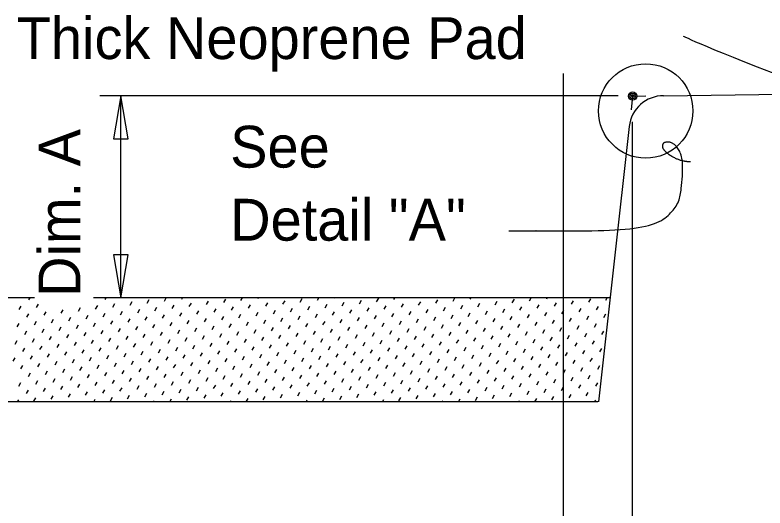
# Model space of a CAD drawing. Extents: x 21516.9 to 21589, y 56156.6 to 56194.3.
# Drawn here: x 21522.743 to 21526.357, y 56182.2 to 56184.575 of the extents above; entities that cross this region are included whole.
import ezdxf

# ---------------------------------------------------------------- set-up
doc = ezdxf.new("R2010")
doc.units = 0
for name, color, linetype in [('AdhocPoint_dp', 7, 'Continuous'), ('Patterning', 7, 'Continuous'), ('PlotBorder_dp', 7, 'Continuous'), ('SheetBorder_dp', 7, 'Continuous')]:
    doc.layers.add(name, color=color, linetype=linetype)

msp = doc.modelspace()

# ---------------------------------------------------------------- linework, layer by layer
at = {"layer": 'AdhocPoint_dp'}
for p, q in [((21525.8686, 56184.1864), (21531.5524, 56184.2643)), ((21525.703, 56184.0381), (21525.5556, 56182.7117)), ((21525.5524, 56182.7117), (21521.6191, 56182.7117))]:
    msp.add_line(p, q, dxfattribs=at)
msp.add_arc((21525.8686, 56184.0197), 0.1667, 90, 173.6598, dxfattribs=at)
at = {"layer": 'Patterning'}
for p, q in [((21522.8378, 56183.2117), (21521.6191, 56183.2117)), ((21522.8099, 56183.2019), (21522.8156, 56183.2117)), ((21522.8465, 56183.1652), (21522.8562, 56183.182)), ((21525.6112, 56183.2117), (21523.1214, 56183.2117)), ((21523.1783, 56183.2041), (21523.1827, 56183.2117)), ((21523.2149, 56183.1675), (21523.2246, 56183.1843)), ((21523.2978, 56183.1773), (21523.3075, 56183.194)), ((21523.3808, 56183.187), (21523.3905, 56183.2038)), ((21523.4637, 56183.1967), (21523.4724, 56183.2117)), ((21523.5466, 56183.2064), (21523.5497, 56183.2117)), ((21523.5832, 56183.1698), (21523.593, 56183.1866)), ((21523.6662, 56183.1795), (21523.6759, 56183.1963)), ((21523.7491, 56183.1893), (21523.7588, 56183.2061)), ((21523.8321, 56183.199), (21523.8394, 56183.2117)), ((21523.8687, 56183.1624), (21523.8784, 56183.1792)), ((21523.915, 56183.2087), (21523.9167, 56183.2117)), ((21523.9516, 56183.1721), (21523.9613, 56183.1889)), ((21524.0345, 56183.1818), (21524.0443, 56183.1986)), ((21524.1175, 56183.1915), (21524.1272, 56183.2083)), ((21524.2004, 56183.2013), (21524.2065, 56183.2117)), ((21524.237, 56183.1647), (21524.2467, 56183.1814)), ((21524.2833, 56183.211), (21524.2838, 56183.2117)), ((21524.32, 56183.1744), (21524.3297, 56183.1912)), ((21524.4029, 56183.1841), (21524.4126, 56183.2009)), ((21524.4858, 56183.1938), (21524.4956, 56183.2106)), ((21524.5688, 56183.2035), (21524.5735, 56183.2117)), ((21524.6054, 56183.1669), (21524.6151, 56183.1837)), ((21524.6883, 56183.1767), (21524.698, 56183.1935)), ((21524.7713, 56183.1864), (21524.781, 56183.2032)), ((21524.8542, 56183.1961), (21524.8632, 56183.2117)), ((21524.9371, 56183.2058), (21524.9405, 56183.2117)), ((21524.9737, 56183.1692), (21524.9835, 56183.186)), ((21525.0567, 56183.1789), (21525.0664, 56183.1957)), ((21525.1396, 56183.1887), (21525.1493, 56183.2055)), ((21525.2225, 56183.1984), (21525.2303, 56183.2117)), ((21525.2592, 56183.1618), (21525.2689, 56183.1786)), ((21525.3055, 56183.2081), (21525.3076, 56183.2117)), ((21525.3421, 56183.1715), (21525.3518, 56183.1883)), ((21525.425, 56183.1812), (21525.4348, 56183.198)), ((21525.508, 56183.191), (21525.5177, 56183.2077)), ((21525.5909, 56183.2007), (21525.5973, 56183.2117)), ((21522.7636, 56183.1555), (21522.7733, 56183.1723)), ((21522.8831, 56183.1286), (21522.8929, 56183.1454)), ((21522.9661, 56183.1384), (21522.9758, 56183.1552)), ((21523.049, 56183.1481), (21523.0587, 56183.1649)), ((21523.1319, 56183.1578), (21523.1417, 56183.1746)), ((21523.2515, 56183.1309), (21523.2612, 56183.1477)), ((21523.3344, 56183.1406), (21523.3441, 56183.1574)), ((21523.4174, 56183.1504), (21523.4271, 56183.1672)), ((21523.5003, 56183.1601), (21523.51, 56183.1769)), ((21523.6198, 56183.1332), (21523.6296, 56183.15)), ((21523.7028, 56183.1429), (21523.7125, 56183.1597)), ((21523.7857, 56183.1526), (21523.7954, 56183.1694)), ((21523.9053, 56183.1258), (21523.915, 56183.1426)), ((21523.9882, 56183.1355), (21523.9979, 56183.1523)), ((21524.0711, 56183.1452), (21524.0809, 56183.162)), ((21524.1541, 56183.1549), (21524.1638, 56183.1717)), ((21524.2736, 56183.128), (21524.2833, 56183.1448)), ((21524.3566, 56183.1378), (21524.3663, 56183.1546)), ((21524.4395, 56183.1475), (21524.4492, 56183.1643)), ((21524.5224, 56183.1572), (21524.5322, 56183.174)), ((21524.642, 56183.1303), (21524.6517, 56183.1471)), ((21524.7249, 56183.1401), (21524.7346, 56183.1568)), ((21524.8079, 56183.1498), (21524.8176, 56183.1666)), ((21524.8908, 56183.1595), (21524.9005, 56183.1763)), ((21525.0103, 56183.1326), (21525.0201, 56183.1494)), ((21525.0933, 56183.1423), (21525.103, 56183.1591)), ((21525.1762, 56183.1521), (21525.1859, 56183.1689)), ((21525.2958, 56183.1252), (21525.3055, 56183.142)), ((21525.3787, 56183.1349), (21525.3884, 56183.1517)), ((21525.4616, 56183.1446), (21525.4714, 56183.1614)), ((21525.5446, 56183.1543), (21525.5543, 56183.1711)), ((21522.8002, 56183.1189), (21522.8099, 56183.1357)), ((21522.9197, 56183.092), (21522.9295, 56183.1088)), ((21523.0027, 56183.1018), (21523.0124, 56183.1185)), ((21523.0856, 56183.1115), (21523.0953, 56183.1283)), ((21523.1685, 56183.1212), (21523.1783, 56183.138)), ((21523.2881, 56183.0943), (21523.2978, 56183.1111)), ((21523.371, 56183.104), (21523.3808, 56183.1208)), ((21523.454, 56183.1138), (21523.4637, 56183.1306)), ((21523.5369, 56183.1235), (21523.5466, 56183.1403)), ((21523.6565, 56183.0966), (21523.6662, 56183.1134)), ((21523.7394, 56183.1063), (21523.7491, 56183.1231)), ((21523.8223, 56183.116), (21523.8321, 56183.1328)), ((21523.9419, 56183.0892), (21523.9516, 56183.106)), ((21524.0248, 56183.0989), (21524.0345, 56183.1157)), ((21524.1077, 56183.1086), (21524.1175, 56183.1254)), ((21524.1907, 56183.1183), (21524.2004, 56183.1351)), ((21524.3102, 56183.0914), (21524.32, 56183.1082)), ((21524.3932, 56183.1012), (21524.4029, 56183.118)), ((21524.4761, 56183.1109), (21524.4858, 56183.1277)), ((21524.559, 56183.1206), (21524.5688, 56183.1374)), ((21524.6786, 56183.0937), (21524.6883, 56183.1105)), ((21524.7615, 56183.1034), (21524.7713, 56183.1202)), ((21524.8445, 56183.1132), (21524.8542, 56183.13)), ((21524.9274, 56183.1229), (21524.9371, 56183.1397)), ((21525.0469, 56183.096), (21525.0567, 56183.1128)), ((21525.1299, 56183.1057), (21525.1396, 56183.1225)), ((21525.2128, 56183.1155), (21525.2225, 56183.1322)), ((21525.3324, 56183.0886), (21525.3421, 56183.1054)), ((21525.4153, 56183.0983), (21525.425, 56183.1151)), ((21525.4982, 56183.108), (21525.508, 56183.1248)), ((21525.5812, 56183.1177), (21525.5909, 56183.1345)), ((21522.7539, 56183.0726), (21522.7636, 56183.0894)), ((21522.8368, 56183.0823), (21522.8465, 56183.0991)), ((21522.9563, 56183.0554), (21522.9661, 56183.0722)), ((21523.0393, 56183.0651), (21523.049, 56183.0819)), ((21523.1222, 56183.0749), (21523.1319, 56183.0917)), ((21523.2052, 56183.0846), (21523.2149, 56183.1014)), ((21523.3247, 56183.0577), (21523.3344, 56183.0745)), ((21523.4076, 56183.0674), (21523.4174, 56183.0842)), ((21523.4906, 56183.0772), (21523.5003, 56183.0939)), ((21523.5735, 56183.0869), (21523.5832, 56183.1037)), ((21523.6931, 56183.06), (21523.7028, 56183.0768)), ((21523.776, 56183.0697), (21523.7857, 56183.0865)), ((21523.8589, 56183.0794), (21523.8687, 56183.0962)), ((21523.9785, 56183.0525), (21523.9882, 56183.0693)), ((21524.0614, 56183.0623), (21524.0711, 56183.0791)), ((21524.1444, 56183.072), (21524.1541, 56183.0888)), ((21524.2273, 56183.0817), (21524.237, 56183.0985)), ((21524.3468, 56183.0548), (21524.3566, 56183.0716)), ((21524.4298, 56183.0646), (21524.4395, 56183.0813)), ((21524.5127, 56183.0743), (21524.5224, 56183.0911)), ((21524.5957, 56183.084), (21524.6054, 56183.1008)), ((21524.7152, 56183.0571), (21524.7249, 56183.0739)), ((21524.7981, 56183.0668), (21524.8079, 56183.0836)), ((21524.8811, 56183.0766), (21524.8908, 56183.0934)), ((21524.964, 56183.0863), (21524.9737, 56183.1031)), ((21525.0836, 56183.0594), (21525.0933, 56183.0762)), ((21525.1665, 56183.0691), (21525.1762, 56183.0859)), ((21525.2494, 56183.0788), (21525.2592, 56183.0956)), ((21525.369, 56183.052), (21525.3787, 56183.0688)), ((21525.4519, 56183.0617), (21525.4616, 56183.0785)), ((21525.5349, 56183.0714), (21525.5446, 56183.0882)), ((21522.7905, 56183.036), (21522.8002, 56183.0528)), ((21522.8734, 56183.0457), (21522.8831, 56183.0625)), ((21522.993, 56183.0188), (21523.0027, 56183.0356)), ((21523.0759, 56183.0285), (21523.0856, 56183.0453)), ((21523.1588, 56183.0383), (21523.1685, 56183.0551)), ((21523.2418, 56183.048), (21523.2515, 56183.0648)), ((21523.3613, 56183.0211), (21523.371, 56183.0379)), ((21523.4442, 56183.0308), (21523.454, 56183.0476)), ((21523.5272, 56183.0405), (21523.5369, 56183.0573)), ((21523.6101, 56183.0503), (21523.6198, 56183.0671)), ((21523.7297, 56183.0234), (21523.7394, 56183.0402)), ((21523.8126, 56183.0331), (21523.8223, 56183.0499)), ((21523.8955, 56183.0428), (21523.9053, 56183.0596)), ((21524.0151, 56183.0159), (21524.0248, 56183.0327)), ((21524.098, 56183.0257), (21524.1077, 56183.0425)), ((21524.181, 56183.0354), (21524.1907, 56183.0522)), ((21524.2639, 56183.0451), (21524.2736, 56183.0619)), ((21524.3834, 56183.0182), (21524.3932, 56183.035)), ((21524.4664, 56183.0279), (21524.4761, 56183.0447)), ((21524.5493, 56183.0377), (21524.559, 56183.0545)), ((21524.6323, 56183.0474), (21524.642, 56183.0642)), ((21524.7518, 56183.0205), (21524.7615, 56183.0373)), ((21524.8347, 56183.0302), (21524.8445, 56183.047)), ((21524.9177, 56183.04), (21524.9274, 56183.0567)), ((21525.0006, 56183.0497), (21525.0103, 56183.0665)), ((21525.1202, 56183.0228), (21525.1299, 56183.0396)), ((21525.2031, 56183.0325), (21525.2128, 56183.0493)), ((21525.286, 56183.0422), (21525.2958, 56183.059)), ((21525.4885, 56183.0251), (21525.4982, 56183.0419)), ((21525.5715, 56183.0348), (21525.5812, 56183.0516)), ((21522.7441, 56182.9896), (21522.7539, 56183.0064)), ((21522.8271, 56182.9994), (21522.8368, 56183.0162)), ((21522.91, 56183.0091), (21522.9197, 56183.0259)), ((21523.0296, 56182.9822), (21523.0393, 56182.999)), ((21523.1125, 56182.9919), (21523.1222, 56183.0087)), ((21523.1954, 56183.0017), (21523.2052, 56183.0184)), ((21523.2784, 56183.0114), (21523.2881, 56183.0282)), ((21523.3979, 56182.9845), (21523.4076, 56183.0013)), ((21523.4809, 56182.9942), (21523.4906, 56183.011)), ((21523.5638, 56183.0039), (21523.5735, 56183.0207)), ((21523.6467, 56183.0137), (21523.6565, 56183.0305)), ((21523.7663, 56182.9868), (21523.776, 56183.0036)), ((21523.8492, 56182.9965), (21523.8589, 56183.0133)), ((21523.9322, 56183.0062), (21523.9419, 56183.023)), ((21524.1346, 56182.9891), (21524.1444, 56183.0059)), ((21524.2176, 56182.9988), (21524.2273, 56183.0156)), ((21524.3005, 56183.0085), (21524.3102, 56183.0253)), ((21524.4201, 56182.9816), (21524.4298, 56182.9984)), ((21524.503, 56182.9913), (21524.5127, 56183.0081)), ((21524.5859, 56183.0011), (21524.5957, 56183.0179)), ((21524.6689, 56183.0108), (21524.6786, 56183.0276)), ((21524.7884, 56182.9839), (21524.7981, 56183.0007)), ((21524.8713, 56182.9936), (21524.8811, 56183.0104)), ((21524.9543, 56183.0033), (21524.964, 56183.0201)), ((21525.0372, 56183.0131), (21525.0469, 56183.0299)), ((21525.1568, 56182.9862), (21525.1665, 56183.003)), ((21525.2397, 56182.9959), (21525.2494, 56183.0127)), ((21525.3226, 56183.0056), (21525.3324, 56183.0224)), ((21525.4056, 56183.0154), (21525.4153, 56183.0321)), ((21525.5251, 56182.9885), (21525.5349, 56183.0053)), ((21522.7807, 56182.953), (21522.7905, 56182.9698)), ((21522.8637, 56182.9628), (21522.8734, 56182.9796)), ((21522.9466, 56182.9725), (21522.9563, 56182.9893)), ((21523.0662, 56182.9456), (21523.0759, 56182.9624)), ((21523.1491, 56182.9553), (21523.1588, 56182.9721)), ((21523.232, 56182.965), (21523.2418, 56182.9818)), ((21523.315, 56182.9748), (21523.3247, 56182.9916)), ((21523.4345, 56182.9479), (21523.4442, 56182.9647)), ((21523.5175, 56182.9576), (21523.5272, 56182.9744)), ((21523.6004, 56182.9673), (21523.6101, 56182.9841)), ((21523.6833, 56182.9771), (21523.6931, 56182.9938)), ((21523.8029, 56182.9502), (21523.8126, 56182.967)), ((21523.8858, 56182.9599), (21523.8955, 56182.9767)), ((21523.9688, 56182.9696), (21523.9785, 56182.9864)), ((21524.0517, 56182.9793), (21524.0614, 56182.9961)), ((21524.1712, 56182.9525), (21524.181, 56182.9692)), ((21524.2542, 56182.9622), (21524.2639, 56182.979)), ((21524.3371, 56182.9719), (21524.3468, 56182.9887)), ((21524.4567, 56182.945), (21524.4664, 56182.9618)), ((21524.5396, 56182.9547), (21524.5493, 56182.9715)), ((21524.6225, 56182.9645), (21524.6323, 56182.9812)), ((21524.7055, 56182.9742), (21524.7152, 56182.991)), ((21524.825, 56182.9473), (21524.8347, 56182.9641)), ((21524.908, 56182.957), (21524.9177, 56182.9738)), ((21524.9909, 56182.9667), (21525.0006, 56182.9835)), ((21525.0738, 56182.9765), (21525.0836, 56182.9933)), ((21525.1934, 56182.9496), (21525.2031, 56182.9664)), ((21525.2763, 56182.9593), (21525.286, 56182.9761)), ((21525.3593, 56182.969), (21525.369, 56182.9858)), ((21525.4422, 56182.9787), (21525.4519, 56182.9955)), ((21525.5617, 56182.9519), (21525.5715, 56182.9687)), ((21522.8174, 56182.9164), (21522.8271, 56182.9332)), ((21522.9003, 56182.9262), (21522.91, 56182.9429)), ((21522.9832, 56182.9359), (21522.993, 56182.9527)), ((21523.1028, 56182.909), (21523.1125, 56182.9258)), ((21523.1857, 56182.9187), (21523.1954, 56182.9355)), ((21523.2686, 56182.9284), (21523.2784, 56182.9452)), ((21523.3516, 56182.9382), (21523.3613, 56182.955)), ((21523.4711, 56182.9113), (21523.4809, 56182.9281)), ((21523.5541, 56182.921), (21523.5638, 56182.9378)), ((21523.637, 56182.9307), (21523.6467, 56182.9475)), ((21523.7199, 56182.9404), (21523.7297, 56182.9572)), ((21523.8395, 56182.9136), (21523.8492, 56182.9304)), ((21523.9224, 56182.9233), (21523.9322, 56182.9401)), ((21524.0054, 56182.933), (21524.0151, 56182.9498)), ((21524.0883, 56182.9427), (21524.098, 56182.9595)), ((21524.2078, 56182.9158), (21524.2176, 56182.9326)), ((21524.2908, 56182.9256), (21524.3005, 56182.9424)), ((21524.3737, 56182.9353), (21524.3834, 56182.9521)), ((21524.4933, 56182.9084), (21524.503, 56182.9252)), ((21524.5762, 56182.9181), (21524.5859, 56182.9349)), ((21524.6591, 56182.9278), (21524.6689, 56182.9446)), ((21524.7421, 56182.9376), (21524.7518, 56182.9544)), ((21524.8616, 56182.9107), (21524.8713, 56182.9275)), ((21524.9446, 56182.9204), (21524.9543, 56182.9372)), ((21525.0275, 56182.9301), (21525.0372, 56182.9469)), ((21525.1104, 56182.9399), (21525.1202, 56182.9566)), ((21525.23, 56182.913), (21525.2397, 56182.9298)), ((21525.3129, 56182.9227), (21525.3226, 56182.9395)), ((21525.3959, 56182.9324), (21525.4056, 56182.9492)), ((21525.4788, 56182.9421), (21525.4885, 56182.9589)), ((21522.7344, 56182.9067), (21522.7441, 56182.9235)), ((21522.854, 56182.8798), (21522.8637, 56182.8966)), ((21522.9369, 56182.8895), (21522.9466, 56182.9063)), ((21523.0198, 56182.8993), (21523.0296, 56182.9161)), ((21523.1394, 56182.8724), (21523.1491, 56182.8892)), ((21523.2223, 56182.8821), (21523.232, 56182.8989)), ((21523.3053, 56182.8918), (21523.315, 56182.9086)), ((21523.3882, 56182.9016), (21523.3979, 56182.9183)), ((21523.5077, 56182.8747), (21523.5175, 56182.8915)), ((21523.5907, 56182.8844), (21523.6004, 56182.9012)), ((21523.6736, 56182.8941), (21523.6833, 56182.9109)), ((21523.7566, 56182.9038), (21523.7663, 56182.9206)), ((21523.8761, 56182.877), (21523.8858, 56182.8937)), ((21523.959, 56182.8867), (21523.9688, 56182.9035)), ((21524.042, 56182.8964), (21524.0517, 56182.9132)), ((21524.1249, 56182.9061), (21524.1346, 56182.9229)), ((21524.2445, 56182.8792), (21524.2542, 56182.896)), ((21524.3274, 56182.889), (21524.3371, 56182.9058)), ((21524.4103, 56182.8987), (21524.4201, 56182.9155)), ((21524.5299, 56182.8718), (21524.5396, 56182.8886)), ((21524.6128, 56182.8815), (21524.6225, 56182.8983)), ((21524.6958, 56182.8912), (21524.7055, 56182.908)), ((21524.7787, 56182.901), (21524.7884, 56182.9178)), ((21524.8982, 56182.8741), (21524.908, 56182.8909)), ((21524.9812, 56182.8838), (21524.9909, 56182.9006)), ((21525.0641, 56182.8935), (21525.0738, 56182.9103)), ((21525.147, 56182.9032), (21525.1568, 56182.92)), ((21525.2666, 56182.8764), (21525.2763, 56182.8932)), ((21525.3495, 56182.8861), (21525.3593, 56182.9029)), ((21525.4325, 56182.8958), (21525.4422, 56182.9126)), ((21525.5154, 56182.9055), (21525.5251, 56182.9223)), ((21522.771, 56182.8701), (21522.7807, 56182.8869)), ((21522.8906, 56182.8432), (21522.9003, 56182.86)), ((21522.9735, 56182.8529), (21522.9832, 56182.8697)), ((21523.0564, 56182.8627), (21523.0662, 56182.8795)), ((21523.176, 56182.8358), (21523.1857, 56182.8526)), ((21523.2589, 56182.8455), (21523.2686, 56182.8623)), ((21523.3419, 56182.8552), (21523.3516, 56182.872)), ((21523.4248, 56182.8649), (21523.4345, 56182.8817)), ((21523.5443, 56182.8381), (21523.5541, 56182.8549)), ((21523.6273, 56182.8478), (21523.637, 56182.8646)), ((21523.7102, 56182.8575), (21523.7199, 56182.8743)), ((21523.7932, 56182.8672), (21523.8029, 56182.884)), ((21523.9127, 56182.8403), (21523.9224, 56182.8571)), ((21523.9956, 56182.8501), (21524.0054, 56182.8669)), ((21524.0786, 56182.8598), (21524.0883, 56182.8766)), ((21524.1615, 56182.8695), (21524.1712, 56182.8863)), ((21524.2811, 56182.8426), (21524.2908, 56182.8594)), ((21524.364, 56182.8524), (21524.3737, 56182.8691)), ((21524.4469, 56182.8621), (21524.4567, 56182.8789)), ((21524.5665, 56182.8352), (21524.5762, 56182.852)), ((21524.6494, 56182.8449), (21524.6591, 56182.8617)), ((21524.7324, 56182.8546), (21524.7421, 56182.8714)), ((21524.8153, 56182.8644), (21524.825, 56182.8812)), ((21524.9348, 56182.8375), (21524.9446, 56182.8543)), ((21525.0178, 56182.8472), (21525.0275, 56182.864)), ((21525.1007, 56182.8569), (21525.1104, 56182.8737)), ((21525.1837, 56182.8666), (21525.1934, 56182.8834)), ((21525.3032, 56182.8398), (21525.3129, 56182.8565)), ((21525.3861, 56182.8495), (21525.3959, 56182.8663)), ((21525.4691, 56182.8592), (21525.4788, 56182.876)), ((21525.552, 56182.8689), (21525.5617, 56182.8857)), ((21522.8076, 56182.8335), (21522.8174, 56182.8503)), ((21522.9272, 56182.8066), (21522.9369, 56182.8234)), ((21523.0101, 56182.8163), (21523.0198, 56182.8331)), ((21523.0931, 56182.8261), (21523.1028, 56182.8428)), ((21523.2126, 56182.7992), (21523.2223, 56182.816)), ((21523.2955, 56182.8089), (21523.3053, 56182.8257)), ((21523.3785, 56182.8186), (21523.3882, 56182.8354)), ((21523.4614, 56182.8283), (21523.4711, 56182.8451)), ((21523.581, 56182.8015), (21523.5907, 56182.8182)), ((21523.6639, 56182.8112), (21523.6736, 56182.828)), ((21523.7468, 56182.8209), (21523.7566, 56182.8377)), ((21523.8298, 56182.8306), (21523.8395, 56182.8474)), ((21523.9493, 56182.8037), (21523.959, 56182.8205)), ((21524.0322, 56182.8135), (21524.042, 56182.8303)), ((21524.1152, 56182.8232), (21524.1249, 56182.84)), ((21524.1981, 56182.8329), (21524.2078, 56182.8497)), ((21524.3177, 56182.806), (21524.3274, 56182.8228)), ((21524.4006, 56182.8157), (21524.4103, 56182.8325)), ((21524.4835, 56182.8255), (21524.4933, 56182.8423)), ((21524.686, 56182.8083), (21524.6958, 56182.8251)), ((21524.769, 56182.818), (21524.7787, 56182.8348)), ((21524.8519, 56182.8277), (21524.8616, 56182.8445)), ((21524.9714, 56182.8009), (21524.9812, 56182.8177)), ((21525.0544, 56182.8106), (21525.0641, 56182.8274)), ((21525.1373, 56182.8203), (21525.147, 56182.8371)), ((21525.2203, 56182.83), (21525.23, 56182.8468)), ((21525.3398, 56182.8031), (21525.3495, 56182.8199)), ((21525.4227, 56182.8129), (21525.4325, 56182.8297)), ((21525.5057, 56182.8226), (21525.5154, 56182.8394)), ((21522.7613, 56182.7872), (21522.771, 56182.804)), ((21522.8442, 56182.7969), (21522.854, 56182.8137)), ((21522.9638, 56182.77), (21522.9735, 56182.7868)), ((21523.0467, 56182.7797), (21523.0564, 56182.7965)), ((21523.1297, 56182.7894), (21523.1394, 56182.8062)), ((21523.3321, 56182.7723), (21523.3419, 56182.7891)), ((21523.4151, 56182.782), (21523.4248, 56182.7988)), ((21523.498, 56182.7917), (21523.5077, 56182.8085)), ((21523.6176, 56182.7648), (21523.6273, 56182.7816)), ((21523.7005, 56182.7746), (21523.7102, 56182.7914)), ((21523.7834, 56182.7843), (21523.7932, 56182.8011)), ((21523.8664, 56182.794), (21523.8761, 56182.8108)), ((21523.9859, 56182.7671), (21523.9956, 56182.7839)), ((21524.0689, 56182.7769), (21524.0786, 56182.7936)), ((21524.1518, 56182.7866), (21524.1615, 56182.8034)), ((21524.2347, 56182.7963), (21524.2445, 56182.8131)), ((21524.3543, 56182.7694), (21524.364, 56182.7862)), ((21524.4372, 56182.7791), (21524.4469, 56182.7959)), ((21524.5202, 56182.7889), (21524.5299, 56182.8057)), ((21524.6031, 56182.7986), (21524.6128, 56182.8154)), ((21524.7226, 56182.7717), (21524.7324, 56182.7885)), ((21524.8056, 56182.7814), (21524.8153, 56182.7982)), ((21524.8885, 56182.7911), (21524.8982, 56182.8079)), ((21525.0081, 56182.7643), (21525.0178, 56182.7811)), ((21525.091, 56182.774), (21525.1007, 56182.7908)), ((21525.1739, 56182.7837), (21525.1837, 56182.8005)), ((21525.2569, 56182.7934), (21525.2666, 56182.8102)), ((21525.3764, 56182.7665), (21525.3861, 56182.7833)), ((21525.4594, 56182.7763), (21525.4691, 56182.7931)), ((21525.5423, 56182.786), (21525.552, 56182.8028)), ((21522.7979, 56182.7506), (21522.8076, 56182.7674)), ((21522.8808, 56182.7603), (21522.8906, 56182.7771)), ((21523.0004, 56182.7334), (21523.0101, 56182.7502)), ((21523.0833, 56182.7431), (21523.0931, 56182.7599)), ((21523.1663, 56182.7528), (21523.176, 56182.7696)), ((21523.2492, 56182.7626), (21523.2589, 56182.7794)), ((21523.3687, 56182.7357), (21523.3785, 56182.7525)), ((21523.4517, 56182.7454), (21523.4614, 56182.7622)), ((21523.5346, 56182.7551), (21523.5443, 56182.7719)), ((21523.6542, 56182.7282), (21523.6639, 56182.745)), ((21523.7371, 56182.738), (21523.7468, 56182.7548)), ((21523.82, 56182.7477), (21523.8298, 56182.7645)), ((21523.903, 56182.7574), (21523.9127, 56182.7742)), ((21524.0225, 56182.7305), (21524.0322, 56182.7473)), ((21524.1055, 56182.7402), (21524.1152, 56182.757)), ((21524.1884, 56182.75), (21524.1981, 56182.7668)), ((21524.2713, 56182.7597), (21524.2811, 56182.7765)), ((21524.3909, 56182.7328), (21524.4006, 56182.7496)), ((21524.4738, 56182.7425), (21524.4835, 56182.7593)), ((21524.5568, 56182.7523), (21524.5665, 56182.769)), ((21524.6397, 56182.762), (21524.6494, 56182.7788)), ((21524.7592, 56182.7351), (21524.769, 56182.7519)), ((21524.8422, 56182.7448), (21524.8519, 56182.7616)), ((21524.9251, 56182.7545), (21524.9348, 56182.7713)), ((21525.0447, 56182.7276), (21525.0544, 56182.7444)), ((21525.1276, 56182.7374), (21525.1373, 56182.7542)), ((21525.2105, 56182.7471), (21525.2203, 56182.7639)), ((21525.2935, 56182.7568), (21525.3032, 56182.7736)), ((21525.413, 56182.7299), (21525.4227, 56182.7467)), ((21525.496, 56182.7397), (21525.5057, 56182.7564)), ((21522.7559, 56182.7117), (21522.7613, 56182.721)), ((21522.8345, 56182.7139), (21522.8442, 56182.7307)), ((21522.9175, 56182.7237), (21522.9272, 56182.7405)), ((21523.0457, 56182.7117), (21523.0467, 56182.7136)), ((21523.123, 56182.7117), (21523.1297, 56182.7233)), ((21523.2029, 56182.7162), (21523.2126, 56182.733)), ((21523.2858, 56182.726), (21523.2955, 56182.7427)), ((21523.4127, 56182.7117), (21523.4151, 56182.7159)), ((21523.49, 56182.7117), (21523.498, 56182.7256)), ((21523.5712, 56182.7185), (21523.581, 56182.7353)), ((21523.7797, 56182.7117), (21523.7834, 56182.7181)), ((21523.857, 56182.7117), (21523.8664, 56182.7279)), ((21523.9396, 56182.7208), (21523.9493, 56182.7376)), ((21524.1468, 56182.7117), (21524.1518, 56182.7204)), ((21524.225, 56182.7134), (21524.2347, 56182.7302)), ((21524.3079, 56182.7231), (21524.3177, 56182.7399)), ((21524.4365, 56182.7117), (21524.4372, 56182.713)), ((21524.5138, 56182.7117), (21524.5202, 56182.7227)), ((21524.5934, 56182.7156), (21524.6031, 56182.7324)), ((21524.6763, 56182.7254), (21524.686, 56182.7422)), ((21524.8035, 56182.7117), (21524.8056, 56182.7153)), ((21524.8808, 56182.7117), (21524.8885, 56182.725)), ((21524.9617, 56182.7179), (21524.9714, 56182.7347)), ((21525.1706, 56182.7117), (21525.1739, 56182.7176)), ((21525.2479, 56182.7117), (21525.2569, 56182.7273)), ((21525.3301, 56182.7202), (21525.3398, 56182.737)), ((21525.5376, 56182.7117), (21525.5423, 56182.7198))]:
    msp.add_line(p, q, dxfattribs=at)
at = {"layer": 'PlotBorder_dp'}
for p, q in [((21525.3858, 56180.8073), (21525.3858, 56184.294)), ((21525.65, 56184.1864), (21523.1528, 56184.1864)), ((21523.2529, 56183.2118), (21523.2529, 56184.1864)), ((21525.7192, 56184.1843), (21525.7119, 56184.118)), ((21525.7192, 56184.1843), (21525.7824, 56184.1852)), ((21525.7191, 56180.1098), (21525.7191, 56184.061))]:
    msp.add_line(p, q, dxfattribs=at)
for points in [[(21523.2529, 56184.1864), (21523.2176, 56183.9781), (21523.2881, 56183.9781)], [(21523.2529, 56183.2118), (21523.2881, 56183.42), (21523.2176, 56183.42)]]:
    msp.add_lwpolyline(points, close=True, dxfattribs=at)
for centre, radius in [((21525.7822, 56184.1127), 0.2273), ((21525.7192, 56184.1843), 0.0199), ((21525.7192, 56184.1843), 0.0131), ((21525.7192, 56184.1843), 0.00592)]:
    msp.add_circle(centre, radius, dxfattribs=at)
for points, degree in [([(21525.9634, 56184.4732), (21525.9741, 56184.4686), (21526.13, 56184.3913), (21526.6357, 56184.2081)], 3), ([(21525.1227, 56183.5353), (21525.2107, 56183.5353), (21525.7768, 56183.5353), (21525.9366, 56183.6352), (21525.9605, 56183.7792), (21525.9605, 56183.9011), (21525.9146, 56183.963), (21525.8627, 56183.963), (21525.8627, 56183.9231), (21525.9485, 56183.8691), (21525.9985, 56183.8691)], 2)]:
    msp.add_open_spline(points, degree=degree, dxfattribs=at)

# ---------------------------------------------------------------- texts
msp.add_text('Thick Neoprene Pad', height=0.2016, dxfattribs=at).set_placement((21522.7517, 56184.3628))
at = {"layer": 'SheetBorder_dp'}
msp.add_text('Dim. A', height=0.2016, rotation=90, dxfattribs=at).set_placement((21523.0582, 56183.2169))
for s, p in [('See ', (21523.7802, 56183.8398)), ('Detail "A" ', (21523.7802, 56183.4878))]:
    msp.add_text(s, height=0.2016, dxfattribs=at).set_placement(p)

doc.saveas('drawing.dxf')
